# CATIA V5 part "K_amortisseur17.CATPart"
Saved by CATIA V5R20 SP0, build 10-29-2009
Part number: amortisseur 17
Publications: "longueur amortisseur", "demi largeur balancier", "epaisseur pieces", "demi largeur tige", "Plan.-55", "liaison 10/17 sur 17", "Droite.1"
Bounding box of the stored display mesh (mm): x -80 to 30, y -799.999 to -386.509, z 105.372 to 309.987
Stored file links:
  G:\Khaled_CFAO_2011\SIL\SIL_GR2\mdardier\Khaled\CAD_ThinkMOTION\K_amortisseur17.CATPart
  G:\Khaled_CFAO_2011\SIL\SIL_GR2\mdardier\Khaled\CAD_ThinkMOTION\K_ass_tandem.CATProduct
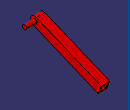
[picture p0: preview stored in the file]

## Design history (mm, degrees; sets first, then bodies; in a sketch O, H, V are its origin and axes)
External parameters (linked from other documents)
  `External.longueur amortisseur` = 410 mm
  `External.demi largeur balancier` = 50 mm
  `External.epaisseur pieces` = 30 mm
  `External.demi largeur tige` = 17.5 mm
Set1
  Plane1 "Plan.-55": linked copy from another document
  Point1 "liaison 10/17 sur 17": linked copy from another document
  Line1: linked copy from another document
Body1 (main body)
  Sketch1 on Plane1, origin (-55, 0, 0), H (0, 1, 0), V (0, 0, 1)
    construction line L1 (-775, 285) -> (-396.0528, 128.4783)
    point P1 (-775, 285)
    line L2 (-765.456, 308.1065) -> (-386.5088, 151.5849)
    line L3 (-405.5968, 105.3718) -> (-784.544, 261.8935)
    arc A1 centre (-775, 285) radius 25 from (-784.544, 261.8935) to (-765.456, 308.1065) cw
    point P4 (-386.5088, 151.5849)
    reference projected point E1 (-775, 285) from Point1
    reference projected line E2 (-775, 285) -> (-396.0528, 128.4783) from Line1
    line L4 (-386.5088, 151.5849) -> (-405.5968, 105.3718)
    point P7 (-386.5088, 151.5849)
    distance L1 L2 = 25 {= `External.demi largeur balancier` /2}
    length L2 = 410 {= `External.longueur amortisseur`}
    tangency: A1 L2, A1 L3
    coincidence: P1 E1, P7 P4
    parallelism: L1 E2
    perpendicularity: L4 L1, L4 L2, L3 L4
  Pad1: profile Sketch1, direction (1, 0, 0), length 25 {= `External.demi largeur balancier` /2}, mirrored extent
  Sketch2 on end face of Pad1, origin (-30, 0, 0), H (0, 1, 0), V (0, 0, 1)
    circle A1 centre (-775, 285) radius 12.5
    point P1 (-775, 285)
    reference projected point E1 (-775, 285) from Point1
    radius A1 = 12.5 {= `External.demi largeur balancier` /4}
    coincidence: P1 E1
  Pad2: profile Sketch2, direction (1, 0, 0), length 60 {= `External.epaisseur pieces` *2}
  Sketch3 on face of Pad1 from Sketch1.L4, origin (0, -383.6648, 158.4703), H (-1, 0, 0), V (0, 0.3818, 0.9243)
    line L1 (36.5, -13.9496) -> (73.5, -13.9496)
    line L2 (73.5, -13.9496) -> (73.5, -50.9496)
    line L3 (73.5, -50.9496) -> (36.5, -50.9496)
    line L4 (36.5, -50.9496) -> (36.5, -13.9496)
    reference projected line E1 (80, -7.4496) -> (30, -7.4496) from edge [face of Pad1 from Sketch1.L2 | face of Pad1 from Sketch1.L4]
    reference projected line E2 (80, -57.4496) -> (80, -7.4496) from edge [start face of Pad1 | face of Pad1 from Sketch1.L4]
    reference projected line E3 (80, -57.4496) -> (30, -57.4496) from edge [face of Pad1 from Sketch1.L4 | face of Pad1 from Sketch1.L3]
    reference projected line E4 (30, -57.4496) -> (30, -7.4496) from edge [face of Pad1 from Sketch1.L4 | end face of Pad1]
    distance L1 E1 = 6.5 {= `External.demi largeur balancier` /2-`External.demi largeur tige` -0.001}
    distance L2 E2 = 6.5 {= `External.demi largeur balancier` /2-`External.demi largeur tige` -0.001}
    distance L3 E3 = 6.5 {= `External.demi largeur balancier` /2-`External.demi largeur tige` -0.001}
    distance E4 L4 = 6.5 {= `External.demi largeur balancier` /2-`External.demi largeur tige` -0.001}
    horizontal: L1 H, L3 H
    vertical: L2 V, L4 V
  Pocket1: profile Sketch3, direction (0, -0.9243, 0.3818), length 360 {= `External.longueur amortisseur` -`External.demi largeur balancier`}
